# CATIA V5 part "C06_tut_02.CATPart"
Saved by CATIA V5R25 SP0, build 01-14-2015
Part number: Part1
Bounding box of the stored display mesh (mm): x -75 to 75, y -125 to 125, z 0 to 28.13
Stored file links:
  E:\ashutosh\Academics\Catia\CATIA V5-6R2013_partfiles\Tutorials_ver_2\C06_tut_02.CATPart
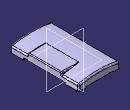
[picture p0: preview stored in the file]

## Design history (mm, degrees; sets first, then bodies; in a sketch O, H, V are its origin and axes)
Body1 (main body)
  Sketch1 on zx-plane, origin (0, 0, 0), H (-1, 0, 0), V (0, 0, 1)
    point P1 (-75, 0)
    line L1 (-75, 0) -> (75, 0)
    line L2 (75, 0) -> (75, 20)
    line L3 (-75, 20) -> (-75, 0)
    point P2 (75, 0)
    point P3 (75, 20)
    arc A1 centre (0, -321.8699) radius 350 from (75, 20) to (-75, 20) ccw
    point P6 (0, 28.1301)
    length L1 = 150
    radius A1 = 350
    distance P3 P2 = 20
    distance V A1 = 350
    coincidence: P1 H, A1 P6, P6 V
    horizontal: L1 H
    vertical: L2 V, L3 V
    symmetry: P2 P1 V
  Pad1: profile Sketch1, direction (0, 1, 0), length 125, mirrored extent
  Plane1: type Offset, RefPlane face of Pad1 from Sketch1.L1, Offset -28, reversed
  Sketch2 on Plane1, origin (0, 0, 28), H (1, 0, 0), V (0, 1, 0)
    line L1 (0, 62.5) -> (75, 62.5)
    line L2 (75, 62.5) -> (75, -62.5)
    line L3 (75, -62.5) -> (0, -62.5)
    line L4 (0, -62.5) -> (0, 62.5)
    reference projected line E1 (75, -125) -> (75, 125) from edge [face of Pad1 from Sketch1.L3 | face of Pad1 from Sketch1.A1]
    length L2 = 125
    distance H L1 = 62.5
    length L3 = 75
    horizontal: L1 H, L3 H
    vertical: L2 V, L4 V
    coincidence: L2 E1
  Pad2: profile Sketch2, direction (0, 0, 1), up to the existing solid (limit type 3)
  Draft1: Angle -3, Neutral face of Pad1 from Sketch1.L1, PullDir face of Pad1 from Sketch1.L1, SupportToDraft (end face of Pad1; face of Pad1; face of Pad1 from Sketch1.L2; start face of Pad1)
  Fillet1: radius 3, on edge [face of Pad2 from Sketch2.L3 | face of Pad2]; edge [face of Pad2 from Sketch2.L1 | face of Pad2]; edge [face of Pad1 | face of Pad2]
  Fillet2: radius 1, on edge [face of Pad1 from Sketch1.A1 | face of Pad2 from Sketch2.L1]
  Fillet3: radius 5, on edge [end face of Pad1 | face of Pad1 from Sketch1.A1]; edge [face of Pad1 from Sketch1.L2 | face of Pad1 from Sketch1.A1]; edge [start face of Pad1 | face of Pad1 from Sketch1.A1]; edge [face of Pad1 | face of Pad1 from Sketch1.A1] (x2); edge [face of Pad1 | end face of Pad1]; edge [start face of Pad1 | face of Pad1]; edge [start face of Pad1 | face of Pad1 from Sketch1.L2]; edge [face of Pad1 from Sketch1.L2 | end face of Pad1]
  Shell1: ExtOffset 0, Face face of Pad1 from Sketch1.L1, IntOffset 2
  Sketch3 on yz-plane, origin (0, 0, 0), H (0, 1, 0), V (0, 0, 1)
    line L1 (-75, 7) -> (75, 7)
    line L2 (75, 7) -> (75, -4.884)
    line L3 (75, -4.884) -> (-75, -4.884)
    line L4 (-75, -4.884) -> (-75, 7)
    point P3 (75, -4.884)
    point P4 (-75, -4.884)
    length L2 = 11.884
    distance H L1 = 7
    length L3 = 150
    horizontal: L1 H, L3 H
    vertical: L2 V, L4 V
    symmetry: P4 P3 V
  Pocket1: profile Sketch3, direction (-1, 0, 0), length 125, mirrored extent
  Sketch4 on zx-plane, origin (0, 0, 0), H (-1, 0, 0), V (0, 0, 1)
    line L1 (-50, 3) -> (50, 3)
    line L2 (50, 3) -> (50, -5.0414)
    line L3 (50, -5.0414) -> (-50, -5.0414)
    line L4 (-50, -5.0414) -> (-50, 3)
    reference projected line E1 (75, 0) -> (-75, 0) from edge [end face of Pad1 | face of Pad1 from Sketch1.L1]
    distance L2 L4 = 100
    distance V L2 = 50
    distance L1 E1 = 3
    horizontal: L1 H, L3 H
    vertical: L2 V, L4 V
  Pocket2: profile Sketch4, direction (0, -1, 0), length 133, mirrored extent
